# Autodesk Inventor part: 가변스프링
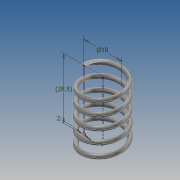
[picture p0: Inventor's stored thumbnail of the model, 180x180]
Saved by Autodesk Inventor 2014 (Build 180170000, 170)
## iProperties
Created: 2018-12
Part Number: 가변스프링
Material: 스테인리스강
Document SubType Name: Modeling
Designer: kb542-15
Density: 8.08 g/cm^3
Appearance: 반연마
Mass: 7.06698 g
Surface Area: 17.7562 cm^2
Volume: 0.874626 cm^3
Author: kb542-15
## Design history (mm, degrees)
sketch "스케치1"
  geometry: L1 (0, 0)-(9, 0); L2 (9, 0)-(9, 28.5); L3 (9, 28.5)-(0, 28.5); L4 (0, 28.5)-(0, 0); C1 r 1 at (9, 0)
  constraints: 8 end point, 2 parallel, 1 centre point, 1 coincident, 1 horizontal, 1 perpendicular
  dimensions: "d0" = 28.5 distance of L1.end L2.end (derived); "d1" = 18 diameter of L2 L4; "d2" = 2 diameter of C1
feature "코일1" pitch "d3" = 10; turns "d5" = 5; dims "d4" = 28.5 (= d0), "d6" = 0, angle "d7" = 90 deg, angle "d8" = 90 deg, "d9" = 0, "d10" = 0
node "작업 평면1"
node "작업 평면2"
sketch "스케치2"
  geometry: L1 (1, 0)-(-1, 0) reference; 1 further point
  constraints: 1 horizontal alignment
  node "절단 모서리 투영1"
sketch "스케치3"
  geometry: L1 (8, 0)-(10, 0) reference; 1 further point
  constraints: 1 horizontal alignment
extrude "돌출1" cut sketch "스케치3" distance "d13" = 10; taper "d14" = 0 deg
extrude "돌출2" cut sketch "스케치2" distance "d15" = 10; taper "d16" = 0 deg
node "솔리드1"
node "절단 모서리 투영2"
other parameters: "d11" = 90 deg, "d12" = 90 deg
